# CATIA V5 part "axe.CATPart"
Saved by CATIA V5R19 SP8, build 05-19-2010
Part number: axe
Bounding box of the stored display mesh (mm): x 66.413 to 80.107, y 24.045 to 37.213, z 57.995 to 71.037
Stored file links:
  G:\EU_thinkMotion\CFAO_2010\MMS_groupe3\MMS_groupe3\A reprendre\amenand\amenand\axe.CATPart
  F:\thinkmotion CFAO v12.1\essuie_glace.CATProduct
  G:\EU_thinkMotion\CFAO_2010\MMS_groupe3\MMS_groupe3\A reprendre\amenand\amenand\bielle.CATPart
  G:\EU_thinkMotion\CFAO_2010\MMS_groupe3\MMS_groupe3\A reprendre\amenand\amenand\bielle_manivelle.CATPart
  G:\EU_thinkMotion\CFAO_2010\MMS_groupe3\MMS_groupe3\A reprendre\amenand\amenand\squelette_axe.CATPart
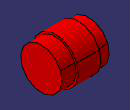
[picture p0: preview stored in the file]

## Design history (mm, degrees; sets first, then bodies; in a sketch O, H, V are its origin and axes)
Set1
  Plane1: linked copy from another document
  DatumCurve1 to DatumCurve5: linked copy from another document
  Line1: linked copy from another document
Body1 (main body)
  Sketch1 on Plane1, origin (83, 30.629, 64.516), H (1, 0, 0), V (0, 0.9927, -0.1203)
    line L1 (-2.8932, 0) -> (-2.8932, -6)
    point P1 (-2.8932, 0)
    line L2 (-2.8932, -6) -> (-7, -6)
    line L3 (-7, -6) -> (-7, -6.6)
    line L4 (-7, -6.6) -> (-13.5869, -6.6)
    line L5 (-13.5869, -6) -> (-16.5869, -6)
    line L6 (-16.5869, -6) -> (-16.5869, 0)
    point P8 (-16.5869, 0)
    line L7 (-13.5869, -6) -> (-13.5869, -6.6)
    line L8 (-16.5869, 0) -> (-2.8932, 0)
    reference projected line E1 (-2.8932, 17.9029) -> (-2.8932, -17.6531) from edge of DatumCurve1
    reference projected point E2 (-13.5869, -7.0635) from DatumCurve3
    reference projected line E3 (-7, 17.9029) -> (-7, -19.0799) from edge of DatumCurve4
    reference projected line E4 (-16.5869, -7.0635) -> (-16.5869, 12.258) from edge of DatumCurve5
    distance L2 L8 = 6
    distance L4 L8 = 6.6
    distance L5 L8 = 6
    coincidence: P1 H, P8 H, L1 E1, L7 E2, L3 E3, L6 E4
    vertical: L1 V, L3 V, L6 V, L7 V
    horizontal: L2 H, L4 H, L5 H, L8 H
  Shaft1: profile Sketch1, axis Line1, angle 360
